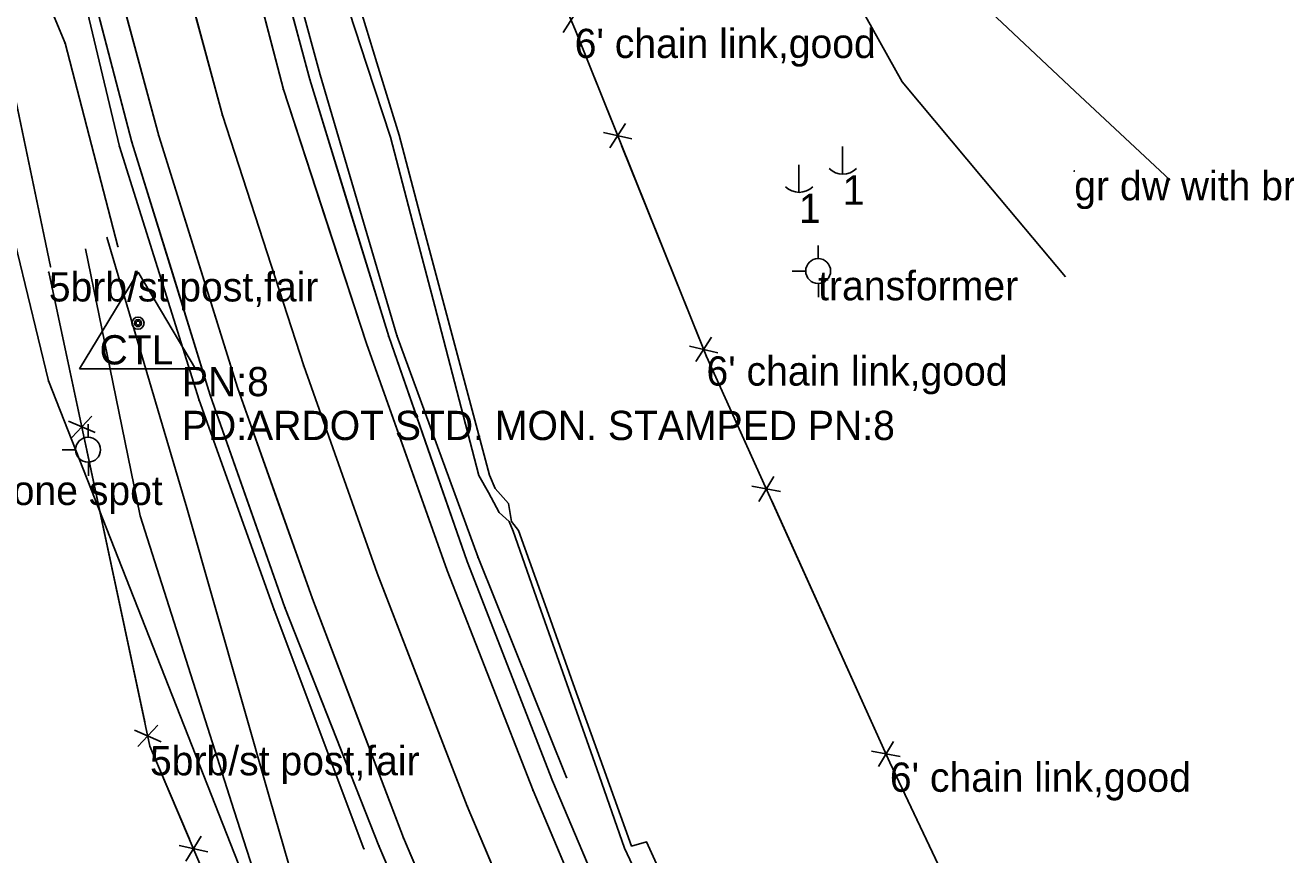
# Model space of a CAD drawing. Extents: x -99999 to 591807, y -99999 to 347168.
# Drawn here: x 588754.4 to 588969.9, y 344591.7 to 344733.6 of the extents above; entities that cross this region are included whole.
import ezdxf

# ---------------------------------------------------------------- set-up
doc = ezdxf.new("R2010")
doc.units = 0
for name, color, linetype in [('S_BREAKLINE', 7, 'Continuous'), ('S_DITCHLINE', 7, 'Continuous'), ('S_DRIVEWAY', 7, 'Continuous'), ('S_EDGE_PAVEMENT', 7, 'Continuous'), ('S_FENCE', 7, 'Continuous'), ('S_FENCE_ANNOT', 7, 'Continuous'), ('S_GRD_PT_SYM', 7, 'Continuous'), ('S_MSC_PT_SYM', 7, 'Continuous'), ('S_PAVEMENT_CROWN', 7, 'Continuous'), ('S_PRIMARY_CTL', 7, 'Continuous'), ('S_PRIMARY_CTL_ANNOT', 7, 'Continuous'), ('S_RDW_PT_SYM', 7, 'Continuous'), ('S_SHOULDER', 7, 'Continuous'), ('S_SURVEY_TEXT_ANNOT', 7, 'Continuous'), ('S_UTILITY_POLE', 7, 'Continuous'), ('S_UTILITY_POLE_ANNOT', 7, 'Continuous'), ('S_UTL_PT_SYM', 7, 'Continuous'), ('S_WATER_UTILITIES', 7, 'Continuous')]:
    doc.layers.add(name, color=color, linetype=linetype)

msp = doc.modelspace()

# ---------------------------------------------------------------- linework, layer by layer
at = {"layer": 'S_BREAKLINE'}
for points in [[(588710.16, 345025.72), (588716.64, 344979.97), (588724.19, 344935.8), (588729.64, 344903.08), (588736.65, 344865.21), (588741.01, 344841.85), (588749.45, 344801.1), (588760.45, 344755.23), (588770.53, 344712.84), (588784.15, 344669.43), (588796.97, 344633.61), (588812.34, 344592.74)], [(588699.2, 345016.22), (588702.38, 344978.4), (588716.07, 344907.03), (588724.96, 344857.44), (588741.19, 344778.55), (588761.25, 344730.5), (588770.29, 344695.75)], [(588786.74, 344802.14), (588794.45, 344763.46), (588804.85, 344725.08), (588817.98, 344680.52), (588831.84, 344642.53), (588846.97, 344604.95)], [(588751.19, 344728.63), (588758.76, 344692.3)]]:
    msp.add_lwpolyline(points, dxfattribs=at)
at = {"layer": 'S_DITCHLINE'}
for points in [[(588792.01, 344810.86), (588796.38, 344787.21), (588800.76, 344763.57), (588804.79, 344751.29), (588808.82, 344739.01), (588812.85, 344726.73), (588816.88, 344714.45), (588820.65, 344699.98), (588824.42, 344685.51), (588828.19, 344671.03), (588831.96, 344656.56), (588833.61, 344653.64), (588835.46, 344650.26), (588837.15, 344648.73), (588837.82, 344647.07), (588842.59, 344633.52), (588847.35, 344619.97), (588852.12, 344606.41), (588856.89, 344592.86), (588866.5, 344572.39)], [(588792.92, 344810.49), (588798.05, 344787.33), (588803.19, 344764.18), (588806.98, 344751.83), (588810.76, 344739.48), (588814.55, 344727.14), (588818.34, 344714.79), (588822.19, 344700.25), (588826.05, 344685.71), (588829.91, 344671.17), (588833.77, 344656.64), (588834.75, 344654.32), (588837.04, 344651.77), (588837.53, 344648.72), (588838.74, 344647.15), (588843.57, 344633.66), (588848.4, 344620.17), (588853.24, 344606.68), (588858.07, 344593.19), (588860.65, 344593.91), (588866.04, 344581.99)], [(588874, 344433.43), (588866.22, 344447.08), (588858.44, 344460.73), (588850.65, 344477.49), (588842.86, 344494.26), (588835.08, 344511.02), (588827.29, 344527.79), (588820.72, 344542.02), (588814.15, 344556.24), (588807.58, 344570.47), (588801.01, 344584.7), (588796.27, 344601.28), (588791.53, 344617.86), (588786.79, 344634.44), (588782.04, 344651.02), (588775.21, 344674.17), (588768.37, 344697.32)], [(588870.94, 344431.25), (588863.41, 344444.75), (588855.88, 344458.25), (588847.8, 344475.35), (588839.72, 344492.44), (588831.64, 344509.53), (588823.56, 344526.63), (588816.56, 344540.57), (588809.56, 344554.52), (588802.55, 344568.47), (588795.55, 344582.42), (588790.18, 344599.23), (588784.82, 344616.04), (588779.45, 344632.86), (588774.08, 344649.67), (588769.42, 344672.51), (588764.77, 344695.34)]]:
    msp.add_lwpolyline(points, dxfattribs=at)
at = {"layer": 'S_DRIVEWAY'}
for points in [[(588800.67, 344841.53), (588822.92, 344845.64), (588845.18, 344849.75), (588864.87, 344838.71), (588884.55, 344827.67), (588889.1, 344813.36), (588893.65, 344799.05), (588898.19, 344784.74), (588902.74, 344770.43), (588910.17, 344753.98), (588917.6, 344737.54), (588933.85, 344722.31), (588950.1, 344707.08)], [(588804.07, 344816.65), (588827.7, 344815.73), (588851.33, 344814.81), (588864.45, 344806.24), (588871.88, 344787.56), (588879.31, 344768.88), (588885.56, 344757.62), (588891.8, 344746.37), (588898.05, 344735.11), (588904.3, 344723.86), (588918.27, 344707.2), (588932.25, 344690.54)]]:
    msp.add_lwpolyline(points, dxfattribs=at)
at = {"layer": 'S_EDGE_PAVEMENT'}
for points in [[(588765.99, 344870.23), (588770.1, 344848.75), (588778.33, 344805.8), (588788.43, 344761.51), (588798.57, 344722.55), (588812.77, 344679.16), (588826.57, 344640.34), (588841.24, 344602.68), (588861.46, 344554.69), (588881.88, 344512.47), (588899.73, 344477.19), (588918.71, 344440.61), (588942.67, 344395.84), (588961.22, 344360.55), (588983.12, 344320.45), (589003.03, 344283.6), (589022.85, 344247.81), (589044.06, 344210.38), (589062.61, 344176.98)], [(588765.99, 344870.23), (588770.1, 344848.75), (588774.22, 344827.27), (588778.33, 344805.8), (588783.38, 344783.65), (588788.43, 344761.51), (588793.5, 344742.03), (588798.57, 344722.55), (588805.67, 344700.86), (588812.77, 344679.16), (588819.67, 344659.75), (588826.57, 344640.34), (588833.9, 344621.51), (588841.24, 344602.68), (588846.3, 344590.68)], [(588743.11, 344866.97), (588747.6, 344843.06), (588756.03, 344801.96), (588766.15, 344755.9), (588777.27, 344714.68), (588790.72, 344671.64), (588803.52, 344635.49), (588819.08, 344594.61), (588840.01, 344545.27), (588861, 344501.19), (588878.99, 344466.41), (588898.26, 344430.03), (588922.05, 344384.94), (588940.96, 344349.74), (588962.71, 344309.22), (588982.6, 344273.24), (589002.69, 344236.73), (589023.86, 344198.7), (589042.88, 344164.72)], [(588743.11, 344866.97), (588747.6, 344843.06), (588751.82, 344822.51), (588756.03, 344801.96), (588761.09, 344778.93), (588766.15, 344755.9), (588771.71, 344735.29), (588777.27, 344714.68), (588784, 344693.16), (588790.72, 344671.64), (588797.12, 344653.56), (588803.52, 344635.49), (588811.3, 344615.05), (588819.08, 344594.61), (588824.31, 344582.28), (588829.54, 344569.94), (588834.77, 344557.6), (588840.01, 344545.27), (588850.5, 344523.23), (588861, 344501.19), (588870, 344483.8), (588878.99, 344466.41), (588888.63, 344448.22), (588898.26, 344430.03)]]:
    msp.add_lwpolyline(points, dxfattribs=at)
at = {"layer": 'S_FENCE'}
for p, q in [((588818.94, 344803.05), (588848.35, 344732.96)), ((588849.05, 344736.56), (588846.39, 344732.34)), ((588848.35, 344732.96), (588870.87, 344676.94)), ((588751.2, 344728.65), (588758.77, 344692.31)), ((588857.06, 344716.78), (588854.33, 344712.59)), ((588853.26, 344715.25), (588858.13, 344714.12)), ((588758.47, 344691.33), (588775.76, 344610.3)), ((588871.76, 344680.22), (588869.03, 344676.04)), ((588867.96, 344678.7), (588872.83, 344677.56)), ((588870.87, 344676.94), (588902.21, 344607.48)), ((588765.81, 344666.73), (588762.41, 344663.07)), ((588761.81, 344665.87), (588766.41, 344663.92)), ((588882.38, 344656.42), (588879.82, 344652.14)), ((588878.64, 344654.74), (588883.55, 344653.82)), ((588773.09, 344613), (588777.7, 344611.05)), ((588777.1, 344613.86), (588773.69, 344610.2)), ((588775.76, 344610.3), (588798.6, 344556.53)), ((588902.82, 344611.1), (588900.26, 344606.82)), ((588899.09, 344609.42), (588903.99, 344608.5)), ((588902.21, 344607.48), (588913.17, 344584.38)), ((588780.77, 344593.28), (588785.66, 344592.24)), ((588784.54, 344594.88), (588781.89, 344590.64))]:
    msp.add_line(p, q, dxfattribs=at)
for points in [[(588848.35, 344732.96), (588855.03, 344716.34)], [(588751.2, 344728.65), (588758.77, 344692.31)], [(588856.36, 344713.02), (588869.73, 344679.79)], [(588758.47, 344691.33), (588763.6, 344667.3)], [(588870.87, 344676.94), (588880.17, 344656.34)], [(588764.62, 344662.49), (588774.88, 344614.43)], [(588882.03, 344652.22), (588900.61, 344611.02)], [(588775.76, 344610.3), (588782.53, 344594.36)], [(588902.21, 344607.48), (588913.17, 344584.38)]]:
    msp.add_lwpolyline(points, dxfattribs=at)
at = {"layer": 'S_GRD_PT_SYM'}
for points in [[(588761.25, 344730.5), (588761.3, 344730.52), (588761.25, 344730.5), (588761.24, 344730.55), (588761.25, 344730.5), (588761.21, 344730.49), (588761.25, 344730.5), (588761.27, 344730.46)], [(588804.85, 344725.08), (588804.9, 344725.1), (588804.85, 344725.08), (588804.84, 344725.13), (588804.85, 344725.08), (588804.8, 344725.07), (588804.85, 344725.08), (588804.87, 344725.03)], [(588770.53, 344712.84), (588770.58, 344712.85), (588770.53, 344712.84), (588770.52, 344712.88), (588770.53, 344712.84), (588770.48, 344712.82), (588770.53, 344712.84), (588770.55, 344712.79)], [(588770.29, 344695.75), (588770.33, 344695.76), (588770.29, 344695.75), (588770.27, 344695.8), (588770.29, 344695.75), (588770.24, 344695.74), (588770.29, 344695.75), (588770.3, 344695.7)], [(588758.76, 344692.3), (588758.81, 344692.31), (588758.76, 344692.3), (588758.75, 344692.35), (588758.76, 344692.3), (588758.71, 344692.29), (588758.76, 344692.3), (588758.77, 344692.25)], [(588817.98, 344680.52), (588818.03, 344680.53), (588817.98, 344680.52), (588817.97, 344680.56), (588817.98, 344680.52), (588817.94, 344680.5), (588817.98, 344680.52), (588818, 344680.47)], [(588784.15, 344669.43), (588784.2, 344669.44), (588784.15, 344669.43), (588784.13, 344669.47), (588784.15, 344669.43), (588784.1, 344669.41), (588784.15, 344669.43), (588784.17, 344669.38)], [(588831.84, 344642.53), (588831.88, 344642.55), (588831.84, 344642.53), (588831.82, 344642.58), (588831.84, 344642.53), (588831.79, 344642.51), (588831.84, 344642.53), (588831.85, 344642.49)], [(588796.97, 344633.61), (588797.01, 344633.63), (588796.97, 344633.61), (588796.95, 344633.66), (588796.97, 344633.61), (588796.92, 344633.59), (588796.97, 344633.61), (588796.99, 344633.57)], [(588846.97, 344604.95), (588847.01, 344604.97), (588846.97, 344604.95), (588846.95, 344605), (588846.97, 344604.95), (588846.92, 344604.93), (588846.97, 344604.95), (588846.99, 344604.91)], [(588812.34, 344592.74), (588812.39, 344592.76), (588812.34, 344592.74), (588812.33, 344592.79), (588812.34, 344592.74), (588812.3, 344592.73), (588812.34, 344592.74), (588812.36, 344592.7)]]:
    msp.add_lwpolyline(points, close=True, dxfattribs=at)
at = {"layer": 'S_MSC_PT_SYM'}
for points in [[(588848.35, 344732.96), (588848.35, 344733.01), (588848.35, 344732.96), (588848.3, 344732.96), (588848.35, 344732.96), (588848.35, 344732.91), (588848.35, 344732.96), (588848.4, 344732.96)], [(588933.73, 344708.62), (588933.73, 344708.67), (588933.73, 344708.62), (588933.68, 344708.62), (588933.73, 344708.62), (588933.73, 344708.57), (588933.73, 344708.62), (588933.78, 344708.62)], [(588758.77, 344692.31), (588758.77, 344692.36), (588758.77, 344692.31), (588758.72, 344692.31), (588758.77, 344692.31), (588758.77, 344692.26), (588758.77, 344692.31), (588758.82, 344692.31)], [(588758.47, 344691.33), (588758.47, 344691.38), (588758.47, 344691.33), (588758.42, 344691.33), (588758.47, 344691.33), (588758.47, 344691.28), (588758.47, 344691.33), (588758.52, 344691.33)], [(588870.87, 344676.94), (588870.87, 344676.99), (588870.87, 344676.94), (588870.82, 344676.94), (588870.87, 344676.94), (588870.87, 344676.89), (588870.87, 344676.94), (588870.92, 344676.94)], [(588775.76, 344610.3), (588775.76, 344610.35), (588775.76, 344610.3), (588775.71, 344610.3), (588775.76, 344610.3), (588775.76, 344610.25), (588775.76, 344610.3), (588775.81, 344610.3)], [(588902.21, 344607.48), (588902.21, 344607.53), (588902.21, 344607.48), (588902.16, 344607.48), (588902.21, 344607.48), (588902.21, 344607.43), (588902.21, 344607.48), (588902.26, 344607.48)]]:
    msp.add_lwpolyline(points, dxfattribs=at)
at = {"layer": 'S_PAVEMENT_CROWN'}
for points in [[(588754.85, 344868.86), (588758.84, 344848.07), (588767.42, 344803.63), (588777.26, 344758.59), (588788.14, 344718.17), (588802.05, 344675.31), (588814.6, 344639.88), (588830, 344600.03), (588850.96, 344550.4), (588871.75, 344506.93), (588889.5, 344471.89), (588908.57, 344435.16), (588932.29, 344390.63), (588951.38, 344354.91), (588973.01, 344314.97), (588993.1, 344278.53), (589012.71, 344242.08), (589034.18, 344204.28), (589052.82, 344171.66)], [(588754.85, 344868.86), (588758.84, 344848.07), (588763.13, 344825.85), (588767.42, 344803.63), (588772.34, 344781.11), (588777.26, 344758.59), (588782.7, 344738.38), (588788.14, 344718.17), (588795.09, 344696.74), (588802.05, 344675.31), (588808.32, 344657.6), (588814.6, 344639.88), (588822.3, 344619.96), (588830, 344600.03), (588835.24, 344587.63), (588840.48, 344575.22), (588845.72, 344562.81), (588850.96, 344550.4), (588861.35, 344528.67), (588871.75, 344506.93), (588880.62, 344489.41), (588889.5, 344471.89), (588899.03, 344453.53), (588908.57, 344435.16)]]:
    msp.add_lwpolyline(points, dxfattribs=at)
at = {"layer": 'S_PRIMARY_CTL'}
for p, q in [((588773.72, 344691.33), (588763.69, 344674.82)), ((588773.72, 344691.33), (588783.55, 344674.82)), ((588763.69, 344674.82), (588783.55, 344674.82))]:
    msp.add_line(p, q, dxfattribs=at)
for radius in [1.04, 0.609, 0.344]:
    msp.add_circle((588773.72, 344682.63), radius, dxfattribs=at)
at = {"layer": 'S_RDW_PT_SYM'}
for points in [[(588798.57, 344722.55), (588798.62, 344722.57), (588798.57, 344722.55), (588798.56, 344722.6), (588798.57, 344722.55), (588798.52, 344722.54), (588798.57, 344722.55), (588798.59, 344722.5)], [(588803.1, 344724.26), (588803.15, 344724.27), (588803.1, 344724.26), (588803.09, 344724.3), (588803.1, 344724.26), (588803.05, 344724.24), (588803.1, 344724.26), (588803.12, 344724.21)], [(588788.14, 344718.17), (588788.18, 344718.19), (588788.14, 344718.17), (588788.12, 344718.22), (588788.14, 344718.17), (588788.09, 344718.16), (588788.14, 344718.17), (588788.15, 344718.13)], [(588772.68, 344713.58), (588772.73, 344713.6), (588772.68, 344713.58), (588772.67, 344713.63), (588772.68, 344713.58), (588772.64, 344713.57), (588772.68, 344713.58), (588772.7, 344713.53)], [(588777.27, 344714.68), (588777.32, 344714.7), (588777.27, 344714.68), (588777.26, 344714.73), (588777.27, 344714.68), (588777.22, 344714.67), (588777.27, 344714.68), (588777.29, 344714.64)], [(588812.77, 344679.16), (588812.82, 344679.18), (588812.77, 344679.16), (588812.75, 344679.21), (588812.77, 344679.16), (588812.72, 344679.14), (588812.77, 344679.16), (588812.79, 344679.11)], [(588816.56, 344680.32), (588816.61, 344680.34), (588816.56, 344680.32), (588816.55, 344680.37), (588816.56, 344680.32), (588816.52, 344680.3), (588816.56, 344680.32), (588816.58, 344680.27)], [(588802.05, 344675.31), (588802.1, 344675.33), (588802.05, 344675.31), (588802.04, 344675.36), (588802.05, 344675.31), (588802, 344675.3), (588802.05, 344675.31), (588802.07, 344675.27)], [(588790.72, 344671.64), (588790.77, 344671.65), (588790.72, 344671.64), (588790.7, 344671.68), (588790.72, 344671.64), (588790.67, 344671.62), (588790.72, 344671.64), (588790.74, 344671.59)], [(588786.05, 344670.32), (588786.1, 344670.34), (588786.05, 344670.32), (588786.03, 344670.37), (588786.05, 344670.32), (588786, 344670.31), (588786.05, 344670.32), (588786.07, 344670.28)], [(588826.57, 344640.34), (588826.61, 344640.36), (588826.57, 344640.34), (588826.55, 344640.39), (588826.57, 344640.34), (588826.52, 344640.32), (588826.57, 344640.34), (588826.59, 344640.29)], [(588829.98, 344641.87), (588830.02, 344641.89), (588829.98, 344641.87), (588829.96, 344641.92), (588829.98, 344641.87), (588829.93, 344641.85), (588829.98, 344641.87), (588830, 344641.83)], [(588814.6, 344639.88), (588814.64, 344639.89), (588814.6, 344639.88), (588814.58, 344639.92), (588814.6, 344639.88), (588814.55, 344639.86), (588814.6, 344639.88), (588814.62, 344639.83)], [(588798.82, 344633.99), (588798.87, 344634.01), (588798.82, 344633.99), (588798.8, 344634.04), (588798.82, 344633.99), (588798.77, 344633.97), (588798.82, 344633.99), (588798.84, 344633.95)], [(588803.52, 344635.49), (588803.56, 344635.51), (588803.52, 344635.49), (588803.5, 344635.54), (588803.52, 344635.49), (588803.47, 344635.48), (588803.52, 344635.49), (588803.53, 344635.45)], [(588844.53, 344604.38), (588844.58, 344604.4), (588844.53, 344604.38), (588844.51, 344604.43), (588844.53, 344604.38), (588844.49, 344604.36), (588844.53, 344604.38), (588844.55, 344604.34)], [(588841.24, 344602.68), (588841.29, 344602.7), (588841.24, 344602.68), (588841.22, 344602.73), (588841.24, 344602.68), (588841.19, 344602.66), (588841.24, 344602.68), (588841.26, 344602.64)], [(588830, 344600.03), (588830.04, 344600.05), (588830, 344600.03), (588829.98, 344600.08), (588830, 344600.03), (588829.95, 344600.02), (588830, 344600.03), (588830.02, 344599.99)], [(588814.89, 344593.26), (588814.94, 344593.28), (588814.89, 344593.26), (588814.87, 344593.3), (588814.89, 344593.26), (588814.84, 344593.24), (588814.89, 344593.26), (588814.91, 344593.21)], [(588819.08, 344594.61), (588819.12, 344594.63), (588819.08, 344594.61), (588819.06, 344594.66), (588819.08, 344594.61), (588819.03, 344594.59), (588819.08, 344594.61), (588819.1, 344594.57)]]:
    msp.add_lwpolyline(points, close=True, dxfattribs=at)
at = {"layer": 'S_SHOULDER'}
for points in [[(588738.19, 344865.87), (588742.81, 344841.87), (588751.14, 344801.34), (588761.84, 344755.05), (588772.68, 344713.58), (588786.05, 344670.32), (588798.82, 344633.99), (588814.89, 344593.26), (588835.93, 344543.63), (588857.06, 344499.35), (588874.94, 344464.7), (588894.38, 344427.63), (588918.68, 344382.54), (588937.74, 344348.11), (588959.08, 344307.72), (588979.45, 344271.19), (588999.32, 344234.44), (589020.87, 344196.88), (589039.88, 344162.93), (589065.49, 344116.39), (589085.6, 344080.47), (589103.48, 344047.79), (589120.92, 344015.14), (589133.17, 343992.99)], [(588738.19, 344865.87), (588742.81, 344841.87), (588746.97, 344821.61), (588751.14, 344801.34), (588756.49, 344778.2), (588761.84, 344755.05), (588767.26, 344734.32), (588772.68, 344713.58), (588779.37, 344691.95), (588786.05, 344670.32), (588792.43, 344652.16), (588798.82, 344633.99), (588806.85, 344613.62), (588814.89, 344593.26), (588820.15, 344580.85), (588825.41, 344568.44), (588830.67, 344556.03), (588835.93, 344543.63), (588846.5, 344521.49), (588857.06, 344499.35), (588866, 344482.03), (588874.94, 344464.7), (588884.66, 344446.16), (588894.38, 344427.63)], [(588783.95, 344805.76), (588792.82, 344762.54), (588803.1, 344724.26), (588816.56, 344680.32), (588829.98, 344641.87), (588844.53, 344604.38), (588864.68, 344556.8), (588885.33, 344514.26), (588902.84, 344478.66), (588922.04, 344442.41), (588946.39, 344397.88), (588965.14, 344362.58), (588986.97, 344322.29), (589005.45, 344284.66), (589025.19, 344249.51), (589047.29, 344212.37), (589066.61, 344179.41), (589092.47, 344132.5), (589112.82, 344096.51), (589129.8, 344066.12), (589149.16, 344031.26), (589168.63, 343996.79)], [(588783.95, 344805.76), (588788.39, 344784.15), (588792.82, 344762.54), (588797.96, 344743.4), (588803.1, 344724.26), (588809.83, 344702.29), (588816.56, 344680.32), (588823.27, 344661.1), (588829.98, 344641.87), (588837.25, 344623.13), (588844.53, 344604.38), (588849.57, 344592.49), (588854.6, 344580.59), (588859.64, 344568.7), (588864.68, 344556.8), (588875.01, 344535.53), (588885.33, 344514.26), (588894.09, 344496.46), (588902.84, 344478.66), (588912.44, 344460.54), (588922.04, 344442.41), (588928.13, 344431.28)]]:
    msp.add_lwpolyline(points, dxfattribs=at)
at = {"layer": 'S_UTILITY_POLE'}
for p, q in [((588894.13, 344712.83), (588894.13, 344708.1)), ((588886.66, 344709.7), (588886.66, 344704.97)), ((588889.96, 344693.64), (588889.96, 344695.88)), ((588887.86, 344691.5), (588885.54, 344691.5)), ((588890.03, 344687.09), (588890.03, 344689.41)), ((588765.19, 344663.08), (588765.19, 344665.33)), ((588763.1, 344660.95), (588760.77, 344660.95)), ((588765.27, 344656.53), (588765.27, 344658.86))]:
    msp.add_line(p, q, dxfattribs=at)
for centre in [(588889.96, 344691.53), (588765.19, 344660.97)]:
    msp.add_circle(centre, 2.13, dxfattribs=at)
for centre in [(588894.19, 344711.52), (588886.72, 344708.4)]:
    msp.add_arc(centre, 3.41, 226.3972, 313.6028, dxfattribs=at)
at = {"layer": 'S_UTL_PT_SYM'}
msp.add_lwpolyline([(588758.4, 344672.73), (588758.4, 344672.78), (588758.4, 344672.73), (588758.35, 344672.73), (588758.4, 344672.73), (588758.4, 344672.68), (588758.4, 344672.73), (588758.45, 344672.73)], dxfattribs=at)
at = {"layer": 'S_WATER_UTILITIES'}
for p, q in [((588714.52, 344854.07), (588758.4, 344672.73)), ((588758.4, 344672.73), (588851.94, 344435.08))]:
    msp.add_line(p, q, dxfattribs=at)

# ---------------------------------------------------------------- texts
at = {"layer": 'S_FENCE_ANNOT'}
for s, p in [("6' chain link,good", (588848.35, 344727.96)), ('5brb/st post,fair', (588758.47, 344686.33)), ("6' chain link,good", (588870.87, 344671.94)), ('5brb/st post,fair', (588775.76, 344605.3)), ("6' chain link,good", (588902.21, 344602.48))]:
    msp.add_text(s, height=5, dxfattribs=at).set_placement(p)
at = {"layer": 'S_PRIMARY_CTL'}
msp.add_text('CTL', height=5, rotation=360, dxfattribs=at).set_placement((588767.14, 344675.56))
at = {"layer": 'S_PRIMARY_CTL_ANNOT'}
for s, p in [('PN:8', (588781.22, 344670.13)), ('PD:ARDOT STD. MON. STAMPED PN:8', (588781.22, 344662.63))]:
    msp.add_text(s, height=5, dxfattribs=at).set_placement(p)
at = {"layer": 'S_SURVEY_TEXT_ANNOT'}
msp.add_text('gr dw with broken asph', height=5, dxfattribs=at).set_placement((588933.73, 344703.62))
at = {"layer": 'S_UTILITY_POLE_ANNOT'}
for s, p in [('1', (588894.15, 344702.88)), ('1', (588886.68, 344699.76)), ('transformer', (588889.96, 344686.53)), ('3 in one spot', (588739.66, 344651.52))]:
    msp.add_text(s, height=5, dxfattribs=at).set_placement(p)

doc.saveas('drawing.dxf')
